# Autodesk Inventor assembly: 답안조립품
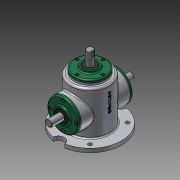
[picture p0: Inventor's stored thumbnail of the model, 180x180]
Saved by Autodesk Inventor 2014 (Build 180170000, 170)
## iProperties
Created: 2018-04
Part Number: 답안조립품
Document SubType Name: Assembly
Designer: NET
Author: NET
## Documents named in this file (16)
- C:\Users\NET\Desktop\480407V1012\답안조립품.iam
- C:\Users\NET\Desktop\480407V1012\본체.ipt
- C:\Users\NET\Desktop\480407V1012\메인 축.ipt
- 메인 축.ipt
- C:\Users\NET\Desktop\480407V1012\서브 축.ipt
- 서브 축.ipt
- C:\Users\NET\Desktop\480407V1012\베어링 6203.ipt
- C:\Users\NET\Desktop\480407V1012\서브 베벨기어.ipt
- C:\Users\NET\Desktop\480407V1012\메인 베벨기어.ipt
- C:\Users\NET\Desktop\480407V1012\키 4x4.ipt
- C:\Users\NET\Desktop\480407V1012\키 5x5.ipt
- C:\Users\NET\Desktop\480407V1012\커버.ipt
- C:\Users\NET\Desktop\480407V1012\오일 실.ipt
- 오일 실.ipt
- C:\Users\NET\Desktop\480407V1012\볼트 M4.ipt
- 볼트 M4.ipt
